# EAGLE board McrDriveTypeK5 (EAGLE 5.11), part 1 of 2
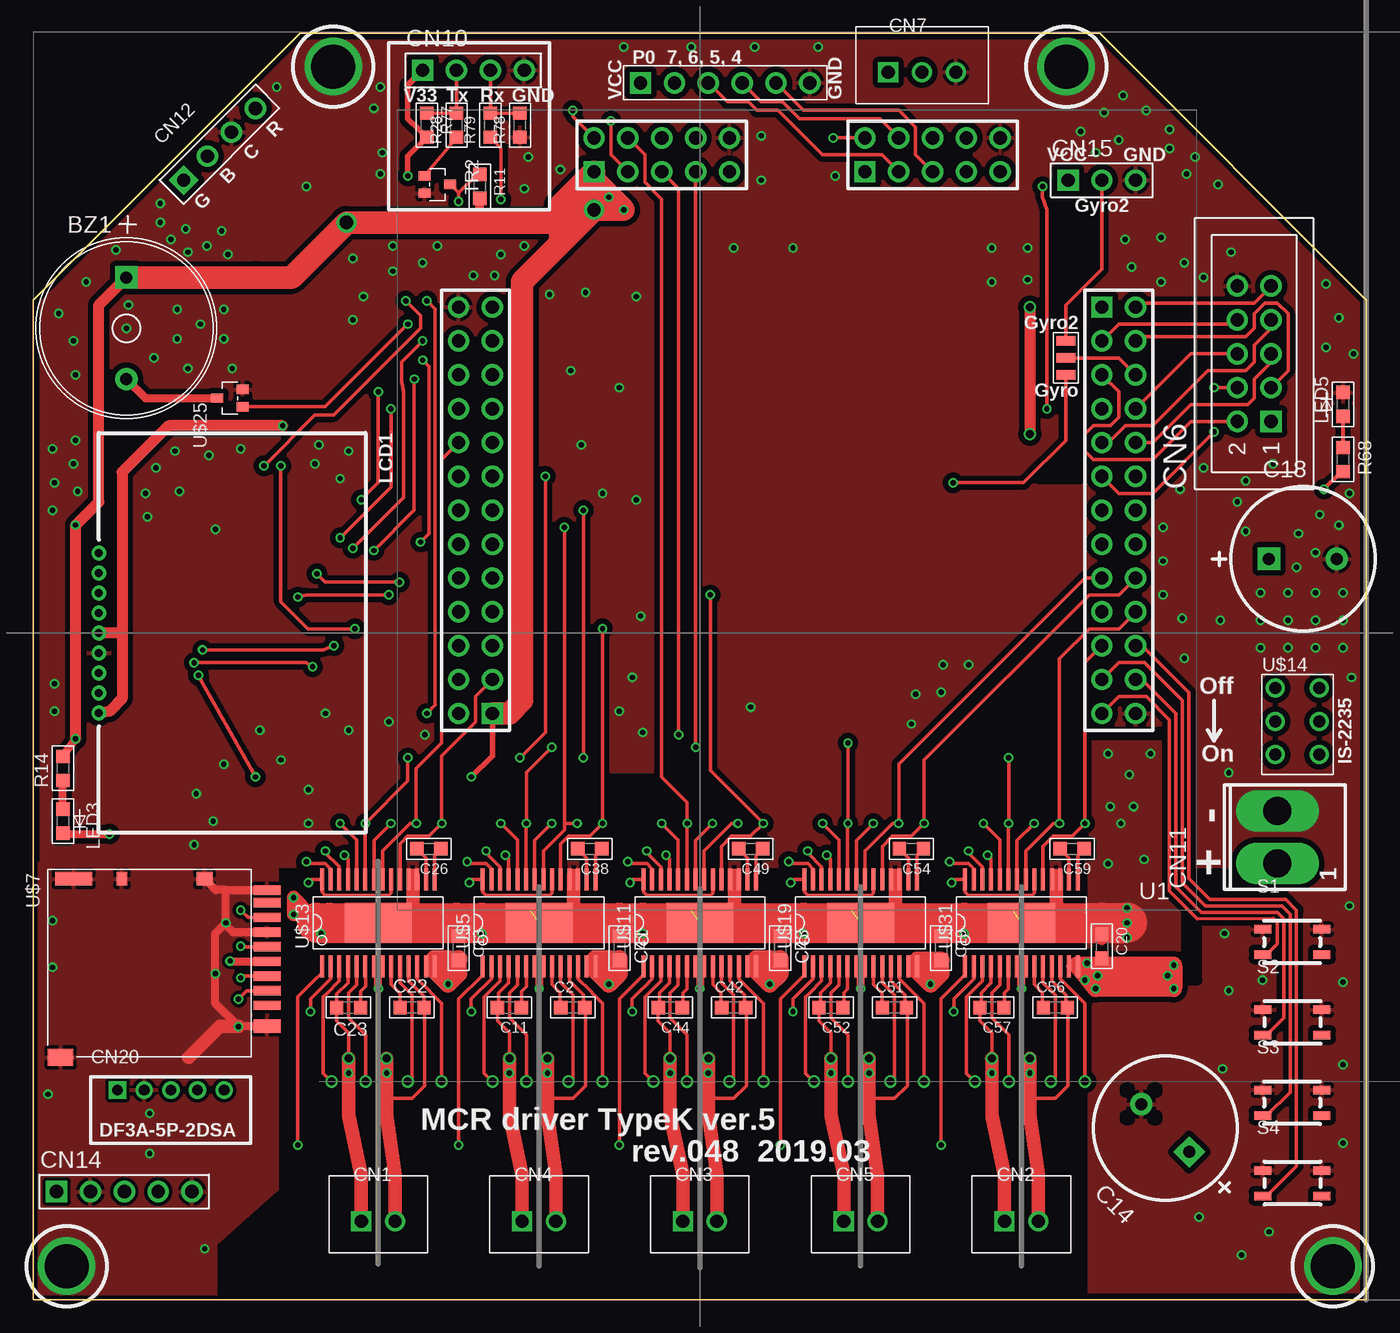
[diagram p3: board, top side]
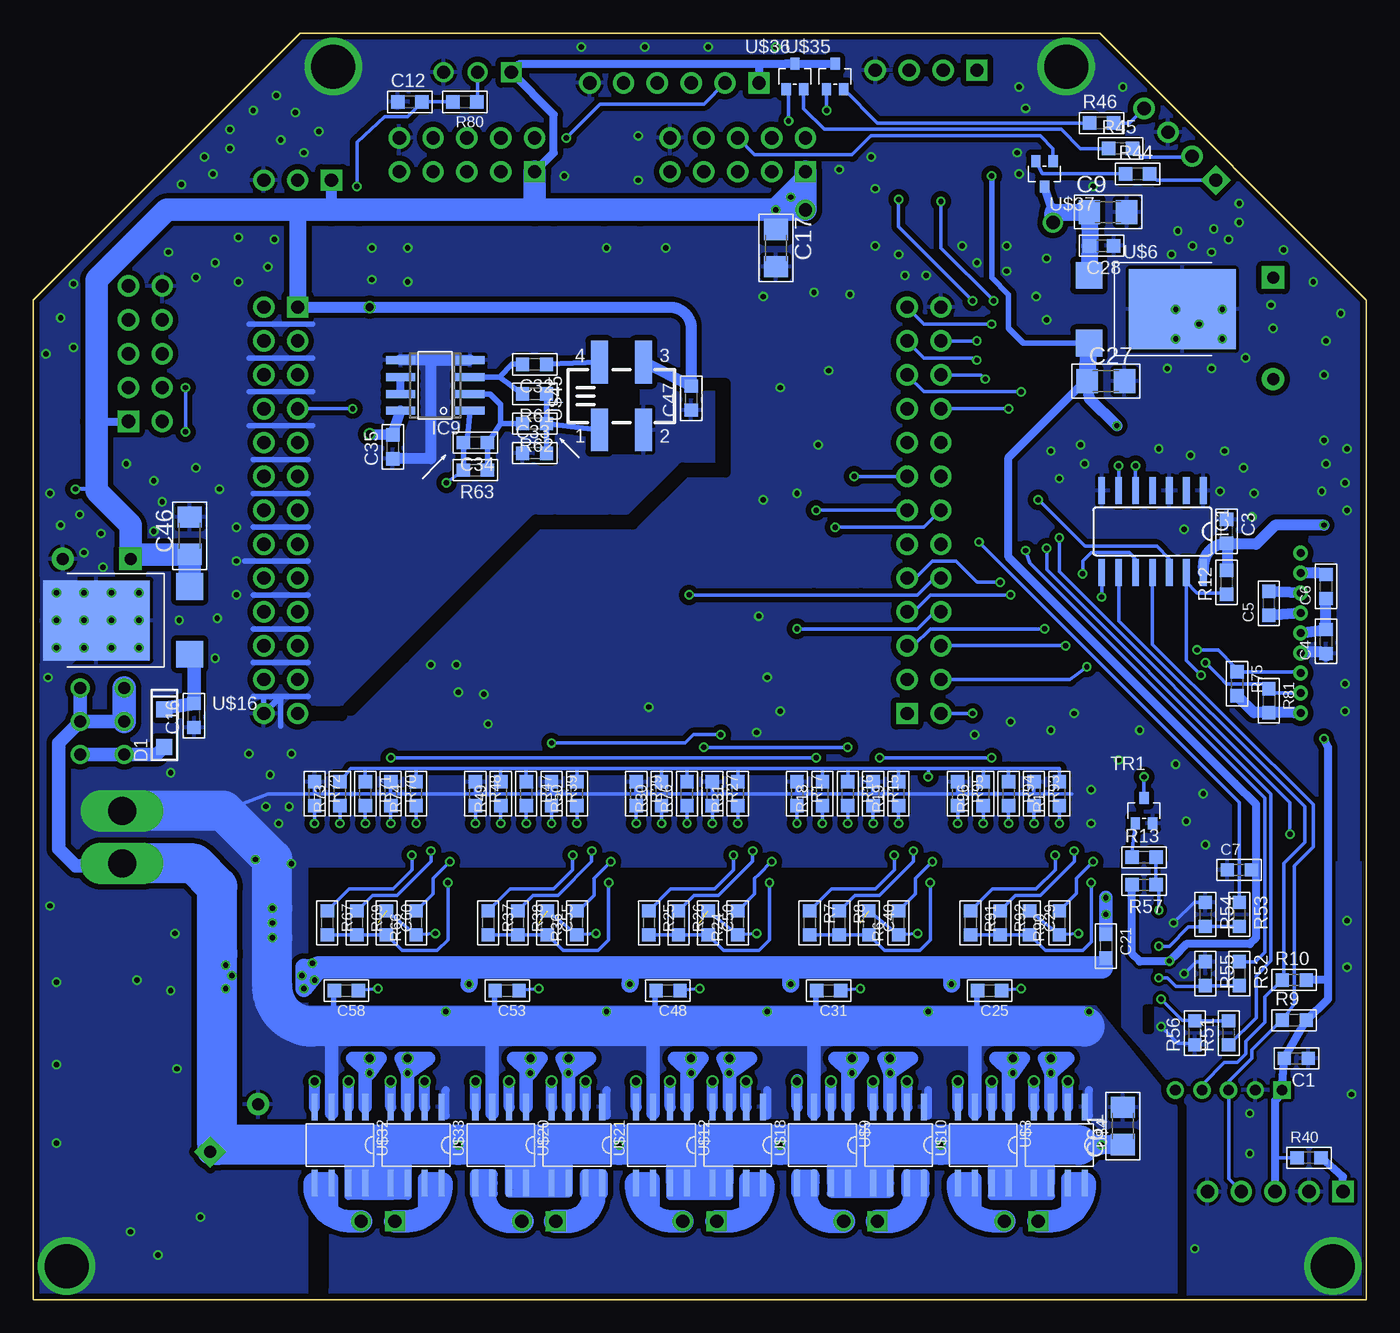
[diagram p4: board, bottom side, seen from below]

Size 100 x 95 mm. Coordinates in mm from the lower left corner, seen from the top.
Copper layers (1*16): Top 0.035mm / dielectric 1.5mm / Bottom 0.035mm
Design rules "Fusion_eagle_rule_v1.1": minimum track width 6mil, minimum drill 12mil, track to track 6mil, track to pad 6mil, pad to pad 6mil, via to via 6mil, smd to smd 0mil, copper to edge 10mil, drill to drill 10mil, minimum pad ring 10mil, minimum via ring 6mil, stop-mask expansion 2mil, vias tented up to drill 100mil, thermal gap 10mil
tRestrict: area 43.3,38.7 to 46.5,39.1; area 79.4,42.4 to 84.8,42.5; area 84,15.6 to 84.3,15.9; area 81.9,15.6 to 82.2,15.9; area 81.9,13.5 to 82.2,13.8; area 84,13.5 to 84.3,13.8; area 86.5,24 to 87.3,30; area 75.4,61.6 to 78.6,61.9
bRestrict: area 54.9,63.8 to 56.8,71.8; area 16.2,20.2 to 16.5,21.9; area 78.3,0.8 to 78.9,2.5; area 55.3,58.2 to 60.9,58.5; area 73.7,86.8 to 74,87.3; area 4.8,57.2 to 5.1,57.5; area 5.9,48.3 to 6,48.7; area 48.1,62.4 to 48.4,68.7; area 48.1,62.1 to 51.3,62.4; area 48.4,68.6 to 49.7,68.7; area 51.1,58.2 to 55.3,62.3; area 72.2,44.2 to 76.4,48.4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

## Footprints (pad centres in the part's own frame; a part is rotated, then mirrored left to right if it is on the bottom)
13B = drill 0.9 pad 1.676 square: + 3.81,0 | drill 0.9 pad 1.676 round: - -3.81,0
C1608C = smd 1 x 1: 1 -0.9,0; 2 0.9,0
C3216 = smd 1.6 x 1.8: 1 -1.4,0; 2 1.4,0
CCAP_10.5 = drill 0.9 pad 1.676 square: + -2.54,0 | drill 0.9 pad 1.676 round: - 2.54,0
2P-XH = drill 1 square: P$1 -1.27,0 | drill 1 round: P$2 1.27,0
ML10 = drill 1 pad 1.6 square: 1 -5.08,-1.27 | drill 1 pad 1.6 round: 2 -5.08,1.27; 3 -2.54,-1.27; 4 -2.54,1.27; 5 0,-1.27; 6 0,1.27; 7 2.54,-1.27; 8 2.54,1.27; 9 5.08,-1.27; 10 5.08,1.27
3P-XH = drill 1 square: P$1 -2.54,0 | drill 1 round: P$2 0,0; P$3 2.54,0
6P-S2 = drill 1 pad 1.6 square: 1 -6.35,0 | drill 1 pad 1.6 round: 2 -3.81,0; 3 -1.27,0; 4 1.27,0; 5 3.81,0; 6 6.35,0
4P-S2 = drill 1 pad 1.6 square: 1 -3.81,0 | drill 1 pad 1.6 round: 2 -1.27,0; 3 1.27,0; 4 3.81,0
2P-VH = drill 2.1 long: 1 0,0; 2 3.96,0
3P-SMD = smd 0.711 x 1.422: P$1 -1.27,0; P$2 0,0; P$3 1.27,0
5P-S2 = drill 1 pad 1.6 square: 1 -5.08,0 | drill 1 pad 1.6 round: 2 -2.54,0; 3 0,0; 4 2.54,0; 5 5.08,0
3P-S2 = drill 1 pad 1.6 square: 1 -2.54,0 | drill 1 pad 1.6 round: 2 0,0; 3 2.54,0
DF3A-5P = drill 0.8 square: P$1 -4,0 | drill 0.8 round: P$2 -2,0; P$3 0,0; P$4 2,0; P$5 4,0
CRG03 = smd 1.2 x 1.2: A -1.4,0; K 1.4,0
SO14 = smd 0.5 x 2.032: 1 -3.81,-3.073; 2 -2.54,-3.073; 3 -1.27,-3.073; 4 0,-3.073; 5 1.27,-3.073; 6 2.54,-3.073; 7 3.81,-3.073; 8 3.81,3.073; 9 2.54,3.073; 10 1.27,3.073; 11 0,3.073; 12 -1.27,3.073; 13 -2.54,3.073; 14 -3.81,3.073
SO08 = smd 0.6 x 2.2: 1 -1.905,-2.6; 2 -0.635,-2.6; 3 0.635,-2.6; 4 1.905,-2.6; 5 1.905,2.6; 6 0.635,2.6; 7 -0.635,2.6; 8 -1.905,2.6
LCD_MINI8X2 = drill 0.6 round: P$1 -6,0; P$2 -4.5,0; P$3 -3,0; P$4 -1.5,0; P$5 0,0; P$6 1.5,0; P$7 3,0; P$8 4.5,0; P$9 6,0
LED_1608B = smd 1 x 1: A -0.9,0; K 0.9,0
TSW_SKRP = smd 1.27 x 0.635: P$1 -2.223,0.953; P$2 2.223,0.953; P$3 -2.223,-0.952; P$4 2.223,-0.953
SC70 = smd 0.7 x 0.9: B -0.65,-0.953; C 0,0.953; E 0.65,-0.953
RY-R8C38 = drill 1 pad 1.6 square: CN3-1 -5.08,-25.4; CN4-1 15.24,-25.4; CN5-1 22.86,15.24; CN6-1 -22.86,-15.24 | drill 1 pad 1.6 round: CN3-2 -5.08,-27.94; CN3-3 -7.62,-25.4; CN3-4 -7.62,-27.94; CN3-5 -10.16,-25.4; CN3-6 -10.16,-27.94; CN3-7 -12.7,-25.4; CN3-8 -12.7,-27.94; CN3-9 -15.24,-25.4; CN3-10 -15.24,-27.94; CN4-2 15.24,-27.94; CN4-3 12.7,-25.4; CN4-4 12.7,-27.94; CN4-5 10.16,-25.4; CN4-6 10.16,-27.94; CN4-7 7.62,-25.4; CN4-8 7.62,-27.94; CN4-9 5.08,-25.4; CN4-10 5.08,-27.94; CN5-2 25.4,15.24; CN5-3 22.86,12.7; CN5-4 25.4,12.7; CN5-5 22.86,10.16; CN5-6 25.4,10.16; CN5-7 22.86,7.62; CN5-8 25.4,7.62; CN5-9 22.86,5.08; CN5-10 25.4,5.08; CN5-11 22.86,2.54; CN5-12 25.4,2.54; CN5-13 22.86,0; CN5-14 25.4,0; CN5-15 22.86,-2.54; CN5-16 25.4,-2.54; CN5-17 22.86,-5.08; CN5-18 25.4,-5.08; CN5-19 22.86,-7.62; CN5-20 25.4,-7.62; CN5-21 22.86,-10.16; CN5-22 25.4,-10.16; CN5-23 22.86,-12.7; CN5-24 25.4,-12.7; CN5-25 22.86,-15.24; CN5-26 25.4,-15.24; CN6-2 -25.4,-15.24; CN6-3 -22.86,-12.7; CN6-4 -25.4,-12.7; CN6-5 -22.86,-10.16; CN6-6 -25.4,-10.16; CN6-7 -22.86,-7.62; CN6-8 -25.4,-7.62; CN6-9 -22.86,-5.08; CN6-10 -25.4,-5.08; CN6-11 -22.86,-2.54; CN6-12 -25.4,-2.54; CN6-13 -22.86,0; CN6-14 -25.4,0; CN6-15 -22.86,2.54; CN6-16 -25.4,2.54; CN6-17 -22.86,5.08; CN6-18 -25.4,5.08; CN6-19 -22.86,7.62; CN6-20 -25.4,7.62; CN6-21 -22.86,10.16; CN6-22 -25.4,10.16; CN6-23 -22.86,12.7; CN6-24 -25.4,12.7; CN6-25 -22.86,15.24; CN6-26 -25.4,15.24
TYPE_K5E = drill 3.3 round: P$2 2.5,2.5; P$4 97.5,2.5; P$5 22.5,92.5; P$6 77.5,92.5
8SOIC = smd 2 x 0.46: P$1 -2.857,1.27; P$2 -2.857,0; P$3 -2.857,-1.27; P$4 -2.857,-2.54; P$5 2.857,-2.54; P$6 2.857,-1.27; P$7 2.857,0; P$8 2.857,1.27
A3941 = smd 0.3 x 1.65: P$1 -4.225,-3.25; P$2 -3.575,-3.25; P$3 -2.925,-3.25; P$4 -2.275,-3.25; P$5 -1.625,-3.25; P$6 -0.975,-3.25; P$7 -0.325,-3.25; P$8 0.325,-3.25; P$9 0.975,-3.25; P$10 1.625,-3.25; P$11 2.275,-3.25; P$12 2.925,-3.25; P$13 3.575,-3.25; P$14 4.225,-3.25; P$15 4.225,3.25; P$16 3.575,3.25; P$17 2.925,3.25; P$18 2.275,3.25; P$19 1.625,3.25; P$20 0.975,3.25; P$21 0.325,3.25; P$22 -0.325,3.25; P$23 -0.975,3.25; P$24 -1.625,3.25; P$25 -2.275,3.25; P$26 -2.925,3.25; P$27 -3.575,3.25; P$28 -4.225,3.25 | smd 5 x 3: P$29 0,0
NJM2391DL1 = smd 8 x 6: GND 7,-2.54 | smd 2 x 2: IN 0,0; OUT 0,-5.08
DM3AT-SF-PEJ = smd 0.7 x 2: P$1 0,0.4; P$2 -1.1,0.4; P$3 -2.2,0.4; P$4 -3.3,0.4; P$5 -4.4,0.4; P$6 -5.5,0.4; P$7 -6.6,0.4; P$8 -7.7,0.4; P$9 -8.65,0.4 | smd 1 x 0.8: P$10 -9.5,-10.5 | smd 1 x 2: P$11 1.55,0.4 | smd 1 x 2.8: P$12 -9.5,-14.11 | smd 1.3 x 1.9: P$13 3.9,-15.1 | smd 1 x 1.2: P$14 -9.5,-4.3
SW-6P-2.5X3.3 = drill 0.9 pad 1.422 round: P$1 0,0; P$2 0,-2.5; P$3 0,-5; P$4 3.3,0; P$5 3.3,-2.5; P$6 3.3,-5
ENC_03R = smd 1.27 x 3.2: P$1 -1.65,-2.54; P$2 1.65,-2.54; P$3 1.65,2.54; P$4 -1.65,2.54

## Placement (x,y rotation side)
BZ1  BUZ  [13B]  6.98,72.87 90 top
C1  0.1u  [C1608C]  5.24,18.1 180 bottom
C2  0.01u  [C1608C]  40.48,21.91 0 top
C3  0.1u  [C1608C]  10.48,57.63 270 bottom
C4  0.1u  [C1608C]  3.02,49.37 90 bottom
C5  1u  [C1608C]  7.3,52.23 90 bottom
C6  1u  [C1608C]  3.02,53.5 90 bottom
C7  0.1u  [C1608C]  9.52,32.23 0 bottom
C9  100u  [C3216]  19.37,81.6 0 bottom
C11  0.01u  [C1608C]  35.72,21.91 180 top
C12  1000p  [C1608C]  71.76,89.85 0 bottom
C13  1u  [C1608C]  31.91,26.35 270 top
C14  1000u  [CCAP_10.5]  84.93,12.86 135 top
C16  1u  [C1608C]  87.95,43.82 90 bottom
C17  100u  [C3216]  44.29,78.9 270 bottom
C18  1000u  [CCAP_10.5]  95.25,55.56 0 top
C19  1u  [C1608C]  68.1,26.35 270 top
C20  1u  [C1608C]  80.17,26.51 270 top
C21  1u  [C1608C]  19.53,26.51 270 bottom
C22  0.01u  [C1608C]  28.42,21.91 0 top
C23  0.01u  [C1608C]  23.65,21.91 180 top
C25  0.22u  [C1608C]  28.26,23.18 180 bottom
C26  0.47u  [C1608C]  29.69,33.81 180 top
C27  100u  [C3216]  19.53,68.9 0 bottom
C28  0.1u  [C1608C]  19.84,79.06 180 bottom
C29  0.1u  [C1608C]  25.24,28.26 270 bottom
C31  0.22u  [C1608C]  40.32,23.18 180 bottom
C32  10u  [C1608C]  62.39,70.17 180 bottom
C33  10u  [C1608C]  62.39,63.5 0 bottom
C34  1000p  [C1608C]  66.83,64.29 180 bottom
C35  0.1u  [C1608C]  73.03,63.98 90 bottom
C38  0.47u  [C1608C]  41.75,33.81 180 top
C40  0.1u  [C1608C]  37.31,28.26 270 bottom
C41  1u  [C1608C]  43.97,26.35 270 top
C42  0.01u  [C1608C]  52.55,21.91 0 top
C43  1u  [C1608C]  56.04,26.35 270 top
C44  0.01u  [C1608C]  47.78,21.91 180 top
C46  100u  [C3216]  88.26,57.31 90 bottom
C47  0.1u  [C1608C]  50.64,67.63 90 bottom
C48  0.22u  [C1608C]  52.39,23.18 180 bottom
C49  0.47u  [C1608C]  53.82,33.81 180 top
C50  0.1u  [C1608C]  49.37,28.26 270 bottom
C51  0.01u  [C1608C]  64.61,21.91 0 top
C52  0.01u  [C1608C]  59.85,21.91 180 top
C53  0.22u  [C1608C]  64.45,23.18 180 bottom
C54  0.47u  [C1608C]  65.88,33.81 180 top
C55  0.1u  [C1608C]  61.44,28.26 270 bottom
C56  0.01u  [C1608C]  76.68,21.91 0 top
C57  0.01u  [C1608C]  71.91,21.91 180 top
C58  0.22u  [C1608C]  76.52,23.18 180 bottom
C59  0.47u  [C1608C]  77.95,33.81 180 top
C60  0.1u  [C1608C]  73.5,28.26 270 bottom
C61  100u  [C3216]  18.26,13.02 90 bottom
CN1  FL  [2P-XH]  25.88,5.87 0 top
CN2  FR  [2P-XH]  74.14,5.87 0 top
CN3  SV  [2P-XH]  50.01,5.87 0 top
CN4  RL  [2P-XH]  37.94,5.87 0 top
CN5  RR  [2P-XH]  62.07,5.87 0 top
CN6  Sensor  [ML10]  91.6,70.96 90 top
CN7  Vol  [3P-XH]  66.67,92.08 0 top
CN8  [6P-S2]  51.91,91.28 0 top
CN10  Bluetooth  [4P-S2]  33.02,92.23 0 top
CN11  [2P-VH]  93.34,32.7 90 top
CN12  FullColorLED  [4P-S2]  13.97,86.68 45 top
CN13  [3P-SMD]  77.47,70.64 90 top
CN14  ENC2  [5P-S2]  6.83,8.1 0 top
CN15  [3P-S2]  80.17,83.98 0 top
CN20  ENC1  [DF3A-5P]  10.32,15.72 0 top
D1  CRG03  [CRG03]  90.17,42.86 90 bottom
IC1  74AC14D  [SO14]  16.03,57.63 180 bottom
IC9  LM358D  [SO08]  69.85,68.58 90 bottom
LCD1  LCD_MINI8X2I2C  [LCD_MINI8X2]  4.92,50.01 270 top
LED3  LED  [LED_1608B]  2.22,35.88 270 top
LED5  VCC  [LED_1608B]  98.27,67.15 90 top
R1  10k  [C1608C]  23.02,37.94 90 bottom
R6  3.3k  [C1608C]  35.08,28.26 90 bottom
R7  10k  [C1608C]  41.75,28.26 270 bottom
R8  10k  [C1608C]  39.53,28.26 270 bottom
R9  10k  [C1608C]  5.4,20.96 0 bottom
R10  10k  [C1608C]  5.4,23.97 0 bottom
R11  10k  [C1608C]  33.5,83.5 270 top
R12  10k  [C1608C]  10.48,53.82 90 bottom
R13  1k  [C1608C]  16.67,33.18 0 bottom
R14  3.3k  [C1608C]  2.22,39.85 90 top
R15  10k  [C1608C]  36.99,37.94 270 bottom
R16  10k  [C1608C]  38.89,37.94 270 bottom
R17  10k  [C1608C]  42.7,37.94 270 bottom
R18  10k  [C1608C]  40.8,37.94 90 bottom
R19  10k  [C1608C]  35.08,37.94 90 bottom
R24  3.3k  [C1608C]  47.15,28.26 90 bottom
R25  10k  [C1608C]  53.82,28.26 270 bottom
R26  10k  [C1608C]  51.59,28.26 270 bottom
R27  10k  [C1608C]  49.05,37.94 270 bottom
R28  1k  [C1608C]  31.75,88.11 90 top
R29  10k  [C1608C]  54.77,37.94 270 bottom
R30  10k  [C1608C]  52.86,37.94 90 bottom
R31  10k  [C1608C]  47.15,37.94 90 bottom
R36  3.3k  [C1608C]  59.21,28.26 90 bottom
R37  10k  [C1608C]  65.88,28.26 270 bottom
R38  10k  [C1608C]  63.66,28.26 270 bottom
R39  10k  [C1608C]  61.12,37.94 270 bottom
R40  2.2k  [C1608C]  4.29,10.64 0 bottom
R44  510  [C1608C]  17.14,84.46 0 bottom
R45  510  [C1608C]  18.41,86.36 0 bottom
R46  510  [C1608C]  19.84,88.27 0 bottom
R47  10k  [C1608C]  63.02,37.94 270 bottom
R48  10k  [C1608C]  66.83,37.94 270 bottom
R49  10k  [C1608C]  64.93,37.94 90 bottom
R50  10k  [C1608C]  59.21,37.94 90 bottom
R51  2.2k  [C1608C]  10.32,20 90 bottom
R52  2.2k  [C1608C]  9.52,24.45 270 bottom
R53  2.2k  [C1608C]  9.52,28.89 270 bottom
R54  3.3k  [C1608C]  12.06,28.89 270 bottom
R55  3.3k  [C1608C]  12.06,24.45 270 bottom
R56  3.3k  [C1608C]  12.86,20 90 bottom
R57  47k  [C1608C]  16.67,31.12 180 bottom
R61  100k  [C1608C]  62.39,67.95 180 bottom
R62  10k  [C1608C]  62.39,65.72 180 bottom
R63  100k  [C1608C]  66.83,62.23 180 bottom
R66  3.3k  [C1608C]  71.28,28.26 90 bottom
R67  10k  [C1608C]  77.95,28.26 270 bottom
R68  3.3k  [C1608C]  98.27,63.02 270 top
R69  10k  [C1608C]  75.72,28.26 270 bottom
R70  10k  [C1608C]  73.18,37.94 270 bottom
R71  10k  [C1608C]  75.09,37.94 270 bottom
R72  10k  [C1608C]  78.9,37.94 270 bottom
R73  10k  [C1608C]  76.99,37.94 90 bottom
R74  10k  [C1608C]  71.28,37.94 90 bottom
R75  10k  [C1608C]  9.68,46.2 270 bottom
R76  10k  [C1608C]  50.96,37.94 90 bottom
R77  56k  [C1608C]  29.53,88.11 270 top
R78  3.3k  [C1608C]  36.51,88.11 90 top
R79  2.2k  [C1608C]  34.29,88.11 90 top
R80  10  [C1608C]  67.63,89.85 180 bottom
R81  10k  [C1608C]  7.3,44.93 270 bottom
R90  3.3k  [C1608C]  23.02,28.26 90 bottom
R91  10k  [C1608C]  29.69,28.26 270 bottom
R92  10k  [C1608C]  27.46,28.26 270 bottom
R93  10k  [C1608C]  24.92,37.94 270 bottom
R94  10k  [C1608C]  26.83,37.94 270 bottom
R95  10k  [C1608C]  30.64,37.94 270 bottom
R96  10k  [C1608C]  28.73,37.94 90 bottom
S1  CL  [TSW_SKRP]  94.46,26.83 0 top
S2  -  [TSW_SKRP]  94.46,20.8 0 top
S3  +  [TSW_SKRP]  94.46,14.76 0 top
S4  OK  [TSW_SKRP]  94.46,8.73 0 top
TR1  2SC1815  [SC70]  16.67,36.67 0 bottom
TR2  2SC1815  [SC70]  30.32,83.66 270 top
U1  RY-R8C38  [RY-R8C38]  57.31,59.21 180 top
U$1  TYPE_K5EE  [TYPE_K5E]  0,0 0 top
U$3  IRF8915  [8SOIC]  28.1,11.59 270 bottom
U$4  IRF8915  [8SOIC]  22.38,11.59 270 bottom
U$5  A3941  [A3941]  37.94,28.26 0 top
U$6  REG_3.3V  [NJM2391DL1]  20.8,76.84 0 bottom
U$7  MicroSD  [DM3AT-SF-PEJ]  17.14,22.07 270 top
U$9  IRF8915  [8SOIC]  40.16,11.59 270 bottom
U$10  IRF8915  [8SOIC]  34.45,11.59 270 bottom
U$11  A3941  [A3941]  50.01,28.26 0 top
U$12  IRF8915  [8SOIC]  52.23,11.59 270 bottom
U$13  A3941  [A3941]  25.88,28.26 0 top
U$14  MainSW  [SW-6P-2.5X3.3]  93.19,45.88 0 top
U$16  REG_5V  [NJM2391DL1]  88.26,48.42 180 bottom
U$18  IRF8915  [8SOIC]  46.51,11.59 270 bottom
U$19  A3941  [A3941]  62.07,28.26 0 top
U$20  IRF8915  [8SOIC]  64.29,11.59 270 bottom
U$21  IRF8915  [8SOIC]  58.58,11.59 270 bottom
U$25  DTR  [SC70]  14.76,67.63 90 top
U$31  A3941  [A3941]  74.14,28.26 0 top
U$32  IRF8915  [8SOIC]  76.36,11.59 270 bottom
U$33  IRF8915  [8SOIC]  70.64,11.59 270 bottom
U$35  DTR  [SC70]  39.85,91.76 0 bottom
U$36  DTR  [SC70]  42.86,91.76 0 bottom
U$37  DTR  [SC70]  24.13,84.46 180 bottom
U$45  ENC_03R  [ENC_03R]  55.88,67.79 0 bottom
